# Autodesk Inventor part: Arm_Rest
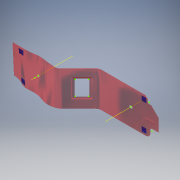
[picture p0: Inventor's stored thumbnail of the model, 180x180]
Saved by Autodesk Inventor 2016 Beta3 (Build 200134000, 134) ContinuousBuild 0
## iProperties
Created: 2007-02
Part Number: Arm_Rest
Document SubType Name: Modeling
Designer: Autodesk, Inc.
Density: 1 g/cm^3
Material: Generic
Appearance: Default
Translation Standard: IGES 5.3
File Name: C:\My Documents\Customer Data\Arm_Rest.igs
Preprocessor: Some Cad System (Microsoft Windows NT Version 5.1 (x86)
Postprocessor: Build: 228, Release: 2008 - Date: Tue 02/06/2007
Sent Units: MM
Uncertainty: 3.1505e-06
Author: Autodesk, Inc.
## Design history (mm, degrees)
feature "Arm Rest"
feature "Nets"
sketch "3D Arm Rest"
sketch "3D Chg_B"
node "X 2400"
pattern_linear "Rectangular Pattern1" dims "d3" = 100
node "Z 2500"
pattern_linear "Rectangular Pattern2" dims "d7" = 100
workaxis "Work Axis2"
  workaxis "Work Axis1"
sketch "Sketch2"
  geometry: C1 r 17.117 at (0, 0)
  constraints: 1 centre point
sketch "Sketch3"
  geometry: L1 (-2839.194, 2558.75)-(-2990.484, 2558.75) reference; L2 (-3009.516, 2558.75)-(-3150, 2558.75) reference; L3 (-3150, 2560)-(-3009.516, 2560) reference; L4 (-2990.484, 2560)-(-2839.194, 2560) reference; L5 (-3009.5, 2560)-(-3009.5, 2558.75) reference; L6 (-2990.5, 2558.75)-(-2990.5, 2560) reference; L7 (-2593.5, 2663.217)-(-2593.5, 2664.455) reference; L8 (-2606.5, 2665.653)-(-2606.5, 2664.401) reference; L9 (-3150, 2558.75)-(-3150, 2560) reference; L10 (-2795.328, 2582.46)-(-2794.444, 2581.576) reference; L11 (-2754.704, 2621.315)-(-2755.588, 2622.199) reference; L12 (-2801.727, 2574.562)-(-2808.385, 2576.346) reference; L13 (-2747.789, 2628.231)-(-2754.704, 2621.315) reference; L14 (-2794.444, 2581.576)-(-2801.359, 2574.661) reference; L15 (-2726.005, 2658.995)-(-2749.375, 2635.625) reference; L16 (-2808.753, 2576.247)-(-2817.097, 2567.903) reference; L17 (-2809.481, 2577.287)-(-2802.399, 2575.389) reference; L18 (-2748.517, 2629.27)-(-2750.415, 2636.353) reference; L19 (-2802.399, 2575.389)-(-2795.328, 2582.46) reference; L20 (-2755.588, 2622.199)-(-2748.517, 2629.27) reference; L21 (-2749.474, 2635.257)-(-2747.69, 2628.599) reference; L22 (-2466.496, 2667.323)-(-2466.566, 2666.072) reference; L23 (-2817.981, 2568.787)-(-2809.481, 2577.287) reference; L24 (-2750.415, 2636.353)-(-2726.889, 2659.879) reference; C1 r 28.379 at (0, 0); A1 r 0.381 centre (-2801.629, 2574.93) between (-2801.727, 2574.562) and (-2801.359, 2574.661) reference; A2 r 0.381 centre (-2748.058, 2628.5) between (-2747.789, 2628.231) and (-2747.69, 2628.599) reference; A3 r 0.381 centre (-2808.483, 2575.978) between (-2808.385, 2576.346) and (-2808.753, 2576.247) reference; A4 r 0.381 centre (-2749.106, 2635.355) between (-2749.375, 2635.625) and (-2749.474, 2635.257) reference; A5 r 31.25 centre (-2839.194, 2590) between (-2839.194, 2558.75) and (-2817.097, 2567.903) reference; 11 further points
  constraints: 1 centre point, 7 other
  node "Project Cut Edges3"
sketch "Sketch7"
  geometry: C1 r 16.625 at (0, 0); 1 further point
  constraints: 1 centre point
node "X 2500"
node "X 2600"
node "X 2700"
node "X 2800"
node "X 2900"
node "X 3000"
node "X 3100"
node "X 3200"
node "z 2600"
node "Z 2700"
body "Srf1"
body "Srf2"
